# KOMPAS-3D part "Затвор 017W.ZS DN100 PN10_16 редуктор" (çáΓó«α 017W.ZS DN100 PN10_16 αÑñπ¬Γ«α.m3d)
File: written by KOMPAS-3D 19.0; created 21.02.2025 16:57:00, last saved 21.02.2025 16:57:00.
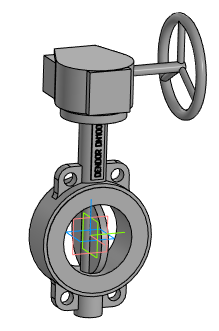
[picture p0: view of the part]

Document properties: Автор: Евгений; Полное имя файла: Затвор 017W.ZS DN100 PN10_16 редуктор.a3d

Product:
- Part/product: Затвор 017W.ZS DN100 PN10_16 редуктор
    Масса: 13.617

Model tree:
1. Операция без истории:1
